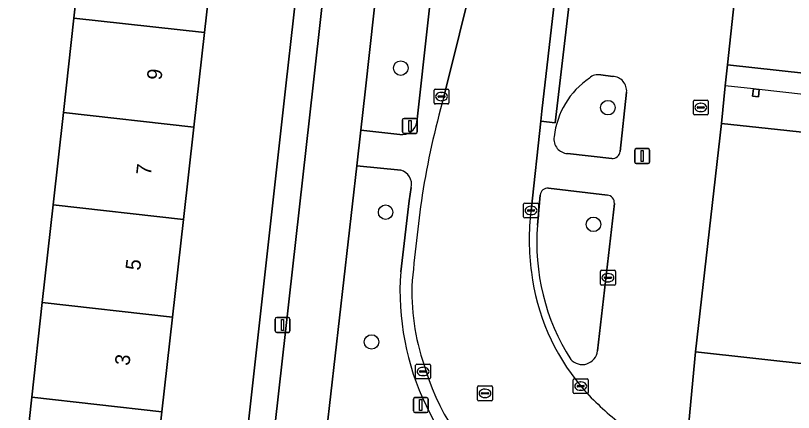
# Model space of a CAD drawing. Extents: x 162026 to 163502, y 387295 to 388169.
# Drawn here: x 162230.9 to 162283.3, y 387554 to 387580.7 of the extents above; entities that cross this region are included whole.
import ezdxf

# ---------------------------------------------------------------- set-up
doc = ezdxf.new("R2010")
doc.units = 0
for name, color, linetype in [('IMGEO_Berm_groen', 7, 'Continuous'), ('IMGEO_Boom', 7, 'Continuous'), ('IMGEO_Brandkraan', 7, 'Continuous'), ('IMGEO_Erf', 7, 'Continuous'), ('IMGEO_Fietspad_gesloten', 7, 'Continuous'), ('IMGEO_Groenvoorziening', 7, 'Continuous'), ('IMGEO_Kolk', 7, 'Continuous'), ('IMGEO_Lichtmast', 7, 'Continuous'), ('IMGEO_Pand', 7, 'Continuous'), ('IMGEO_Pand_nummerreeks', 7, 'Continuous'), ('IMGEO_Pand_overbouw', 7, 'Continuous'), ('IMGEO_Rijbaan_lokaal_gesloten', 7, 'Continuous'), ('IMGEO_Rijbaan_lokaal_open', 7, 'Continuous'), ('IMGEO_Rioolput', 7, 'Continuous'), ('IMGEO_Voetpad_gesloten', 7, 'Continuous'), ('IMGEO_Voetpad_open', 7, 'Continuous')]:
    doc.layers.add(name, color=color, linetype=linetype)

msp = doc.modelspace()

# ---------------------------------------------------------------- linework, layer by layer
at = {"layer": 'IMGEO_Berm_groen'}
for points in [[(162260.156, 387602.193), (162257.445, 387602.487), (162254.47, 387575.568), (162254.178, 387572.997), (162256.814, 387572.706)], [(162257.966, 387573.542), (162261.02, 387601.114)]]:
    msp.add_lwpolyline(points, dxfattribs=at)
msp.add_arc((162256.958, 387573.719), 1.023, 261.9126, 350.0237, dxfattribs=at)
at = {"layer": 'IMGEO_Boom'}
for centre in [(162256.873, 387577.172), (162270.837, 387574.509), (162255.854, 387567.469), (162269.863, 387566.651), (162254.903, 387558.729)]:
    msp.add_circle(centre, 0.489, dxfattribs=at)
at = {"layer": 'IMGEO_Brandkraan'}
for p, q in [((162276.595, 387574.097), (162276.595, 387574.949)), ((162276.67, 387575.023), (162277.522, 387575.023)), ((162277.083, 387574.803), (162277.108, 387574.803)), ((162277.596, 387574.949), (162277.596, 387574.097)), ((162276.854, 387574.517), (162276.854, 387574.529)), ((162277.292, 387574.48), (162276.894, 387574.48)), ((162276.897, 387574.566), (162277.295, 387574.566)), ((162277.106, 387574.243), (162277.081, 387574.243)), ((162277.338, 387574.529), (162277.338, 387574.517)), ((162277.522, 387574.023), (162276.67, 387574.023))]:
    msp.add_line(p, q, dxfattribs=at)
for points in [[(162276.595, 387574.097), (162276.595, 387574.949)], [(162276.67, 387575.023), (162277.522, 387575.023)], [(162277.596, 387574.949), (162277.596, 387574.097)], [(162277.522, 387574.023), (162276.67, 387574.023)]]:
    msp.add_lwpolyline(points, dxfattribs=at)
for centre, radius, start, end in [((162276.672, 387574.947), 0.0765, 91.552, 178.448), ((162276.672, 387574.947), 0.0765, 91.552, 178.448), ((162277.52, 387574.947), 0.0765, 1.552, 88.448), ((162277.52, 387574.947), 0.0765, 1.552, 88.448), ((162276.894, 387574.526), 0.0403, 85.8775, 175.7526), ((162276.891, 387574.516), 0.0366, 178.938, 274.7102), ((162277.295, 387574.523), 0.043, 264.8664, 352.4533), ((162277.299, 387574.528), 0.0386, 1.7309, 96.639), ((162276.672, 387574.099), 0.0765, 181.552, 268.448), ((162276.672, 387574.099), 0.0765, 181.552, 268.448), ((162277.52, 387574.099), 0.0765, 271.552, 358.448), ((162277.52, 387574.099), 0.0765, 271.552, 358.448)]:
    msp.add_arc(centre, radius, start, end, dxfattribs=at)
for centre, major_axis, ratio, start_param, end_param in [((162277.082, 387574.523), (-0.387, 0.002), 0.722429, 4.712389, 7.853982), ((162277.107, 387574.523), (-0.39, 0.002), 0.717154, 1.570796, 4.712389)]:
    msp.add_ellipse(centre, major_axis=major_axis, ratio=ratio, start_param=start_param, end_param=end_param, dxfattribs=at)
at = {"layer": 'IMGEO_Erf'}
for points in [[(162231.278, 387548.466), (162232.005, 387555.004), (162232.714, 387561.383), (162233.446, 387567.963), (162234.136, 387574.175), (162234.844, 387580.545), (162235.554, 387586.926), (162236.264, 387593.317), (162236.974, 387599.708), (162233.45, 387600.1), (162234.133, 387606.237), (162234.161, 387606.49), (162237.685, 387606.098), (162238.394, 387612.479), (162239.105, 387618.87), (162236.083, 387619.207), (162236.755, 387625.24), (162239.776, 387624.903), (162239.812, 387625.23), (162240.54, 387631.778), (162230.472, 387632.88)], [(162245.725, 387545.476), (162249.133, 387575.99), (162253.77, 387617.22), (162255.196, 387630.156), (162249.391, 387630.796), (162248.656, 387624.246), (162247.942, 387617.886), (162247.225, 387611.496), (162246.509, 387605.116), (162245.792, 387598.726), (162245.075, 387592.336), (162244.358, 387585.947), (162243.642, 387579.567), (162242.927, 387573.197), (162242.23, 387566.986), (162241.491, 387560.407), (162240.775, 387554.027), (162240.041, 387547.484)]]:
    msp.add_lwpolyline(points, dxfattribs=at)
at = {"layer": 'IMGEO_Fietspad_gesloten'}
msp.add_lwpolyline([(162249.002, 387527.305), (162250.593, 387541.437), (162251.213, 387546.944), (162251.283, 387547.562), (162253.903, 387570.582), (162254.178, 387572.997), (162254.47, 387575.568), (162257.445, 387602.487), (162257.74, 387604.874), (162260.472, 387629.489), (162260.746, 387631.878), (162262.605, 387648.82), (162263.515, 387657.112), (162260.081, 387657.552), (162255.563, 387617.085), (162250.964, 387576.026), (162247.716, 387547.043), (162245.412, 387526.736)], dxfattribs=at)
at = {"layer": 'IMGEO_Groenvoorziening'}
for points in [[(162271.159, 387576.617), (162270.351, 387576.709)], [(162271.664, 387571.56), (162272.097, 387575.545)], [(162268.107, 387571.421), (162271.091, 387571.092)], [(162256.879, 387570.293), (162253.903, 387570.582), (162251.283, 387547.562), (162254.148, 387547.245), (162255.721, 387547.048), (162268.163, 387545.52)], [(162256.87, 387563.453), (162257.433, 387568.234), (162257.579, 387569.13)], [(162270.803, 387568.62), (162266.833, 387569.082)], [(162266.268, 387568.621), (162266.088, 387566.604)], [(162270.145, 387558.124), (162271.27, 387568.06)]]:
    msp.add_lwpolyline(points, dxfattribs=at)
for centre, radius, start, end in [((162272.692, 387571.946), 5.511, 124.2618, 173.6784), ((162270.162, 387575.901), 0.83, 76.8476, 133.6881), ((162271.113, 387575.631), 0.988, 355.0317, 87.3402), ((162268.17, 387572.388), 0.97, 170.2251, 219.7285), ((162268.169, 387572.388), 0.969, 219.7795, 266.3545), ((162271.136, 387571.622), 0.532, 265.1894, 353.2913), ((162256.606, 387569.337), 0.995, 348.0097, 74.0771), ((162266.783, 387568.567), 0.518, 84.4254, 173.9986), ((162270.756, 387568.106), 0.516, 354.8288, 84.8226), ((162280.669, 387565.415), 14.63, 175.339, 212.4799), ((162274.616, 387562.147), 17.794, 175.7909, 235.5291), ((162269.108, 387558.255), 1.045, 221.7581, 352.7883)]:
    msp.add_arc(centre, radius, start, end, dxfattribs=at)
at = {"layer": 'IMGEO_Kolk'}
for p, q in [((162259.197, 387575.756), (162260.049, 387575.756)), ((162259.122, 387574.83), (162259.122, 387575.682)), ((162259.381, 387575.25), (162259.381, 387575.262)), ((162259.424, 387575.299), (162259.822, 387575.299)), ((162259.61, 387575.536), (162259.635, 387575.536)), ((162259.865, 387575.262), (162259.865, 387575.25)), ((162260.123, 387575.682), (162260.123, 387574.83)), ((162260.049, 387574.756), (162259.197, 387574.756)), ((162259.819, 387575.213), (162259.421, 387575.213)), ((162259.633, 387574.976), (162259.608, 387574.976)), ((162265.156, 387567.159), (162265.156, 387568.011)), ((162265.231, 387568.085), (162266.083, 387568.085)), ((162266.157, 387568.011), (162266.157, 387567.159)), ((162265.415, 387567.579), (162265.415, 387567.591)), ((162265.853, 387567.542), (162265.455, 387567.542)), ((162265.458, 387567.628), (162265.856, 387567.628)), ((162265.644, 387567.865), (162265.669, 387567.865)), ((162265.899, 387567.591), (162265.899, 387567.579)), ((162266.083, 387567.085), (162265.231, 387567.085)), ((162265.667, 387567.305), (162265.642, 387567.305)), ((162270.337, 387562.631), (162270.337, 387563.483)), ((162270.412, 387563.557), (162271.264, 387563.557)), ((162270.825, 387563.337), (162270.85, 387563.337)), ((162271.338, 387563.483), (162271.338, 387562.631)), ((162270.596, 387563.051), (162270.596, 387563.063)), ((162271.034, 387563.014), (162270.636, 387563.014)), ((162270.639, 387563.1), (162271.037, 387563.1)), ((162270.848, 387562.777), (162270.823, 387562.777)), ((162271.08, 387563.063), (162271.08, 387563.051)), ((162271.264, 387562.557), (162270.412, 387562.557)), ((162257.878, 387556.315), (162257.878, 387557.167)), ((162257.953, 387557.241), (162258.805, 387557.241)), ((162258.366, 387557.021), (162258.391, 387557.021)), ((162258.879, 387557.167), (162258.879, 387556.315)), ((162258.137, 387556.735), (162258.137, 387556.747)), ((162258.575, 387556.698), (162258.177, 387556.698)), ((162258.18, 387556.784), (162258.578, 387556.784)), ((162258.389, 387556.461), (162258.364, 387556.461)), ((162258.621, 387556.747), (162258.621, 387556.735)), ((162258.805, 387556.241), (162257.953, 387556.241)), ((162268.504, 387555.328), (162268.504, 387556.18)), ((162268.579, 387556.254), (162269.431, 387556.254)), ((162268.992, 387556.034), (162269.017, 387556.034)), ((162269.505, 387556.18), (162269.505, 387555.328)), ((162268.763, 387555.748), (162268.763, 387555.76)), ((162269.201, 387555.711), (162268.803, 387555.711)), ((162268.806, 387555.797), (162269.204, 387555.797)), ((162269.015, 387555.474), (162268.99, 387555.474)), ((162269.247, 387555.76), (162269.247, 387555.748)), ((162269.431, 387555.254), (162268.579, 387555.254))]:
    msp.add_line(p, q, dxfattribs=at)
for points in [[(162259.197, 387575.756), (162260.049, 387575.756)], [(162259.122, 387574.83), (162259.122, 387575.682)], [(162260.123, 387575.682), (162260.123, 387574.83)], [(162260.049, 387574.756), (162259.197, 387574.756)], [(162265.156, 387567.159), (162265.156, 387568.011)], [(162265.231, 387568.085), (162266.083, 387568.085)], [(162266.157, 387568.011), (162266.157, 387567.159)], [(162266.083, 387567.085), (162265.231, 387567.085)], [(162270.337, 387562.631), (162270.337, 387563.483)], [(162270.412, 387563.557), (162271.264, 387563.557)], [(162271.338, 387563.483), (162271.338, 387562.631)], [(162271.264, 387562.557), (162270.412, 387562.557)], [(162257.878, 387556.315), (162257.878, 387557.167)], [(162257.953, 387557.241), (162258.805, 387557.241)], [(162258.879, 387557.167), (162258.879, 387556.315)], [(162258.805, 387556.241), (162257.953, 387556.241)], [(162268.504, 387555.328), (162268.504, 387556.18)], [(162268.579, 387556.254), (162269.431, 387556.254)], [(162269.505, 387556.18), (162269.505, 387555.328)], [(162269.431, 387555.254), (162268.579, 387555.254)]]:
    msp.add_lwpolyline(points, dxfattribs=at)
for centre, radius, start, end in [((162259.199, 387575.68), 0.0765, 91.552, 178.448), ((162259.199, 387575.68), 0.0765, 91.552, 178.448), ((162260.047, 387575.68), 0.0765, 1.552, 88.448), ((162260.047, 387575.68), 0.0765, 1.552, 88.448), ((162259.421, 387575.259), 0.0403, 85.8775, 175.7526), ((162259.418, 387575.249), 0.0366, 178.938, 274.7102), ((162259.822, 387575.256), 0.043, 264.8664, 352.4533), ((162259.826, 387575.261), 0.0386, 1.7309, 96.639), ((162259.199, 387574.832), 0.0765, 181.552, 268.448), ((162259.199, 387574.832), 0.0765, 181.552, 268.448), ((162260.047, 387574.832), 0.0765, 271.552, 358.448), ((162260.047, 387574.832), 0.0765, 271.552, 358.448), ((162265.233, 387568.009), 0.0765, 91.552, 178.448), ((162265.233, 387568.009), 0.0765, 91.552, 178.448), ((162266.081, 387568.009), 0.0765, 1.552, 88.448), ((162266.081, 387568.009), 0.0765, 1.552, 88.448), ((162265.455, 387567.588), 0.0403, 85.8775, 175.7526), ((162265.452, 387567.578), 0.0366, 178.938, 274.7102), ((162265.856, 387567.585), 0.043, 264.8664, 352.4533), ((162265.86, 387567.59), 0.0386, 1.7309, 96.639), ((162265.233, 387567.161), 0.0765, 181.552, 268.448), ((162265.233, 387567.161), 0.0765, 181.552, 268.448), ((162266.081, 387567.161), 0.0765, 271.552, 358.448), ((162266.081, 387567.161), 0.0765, 271.552, 358.448), ((162270.414, 387563.481), 0.0765, 91.552, 178.448), ((162270.414, 387563.481), 0.0765, 91.552, 178.448), ((162271.262, 387563.481), 0.0765, 1.552, 88.448), ((162271.262, 387563.481), 0.0765, 1.552, 88.448), ((162270.636, 387563.06), 0.0403, 85.8775, 175.7526), ((162270.633, 387563.05), 0.0366, 178.938, 274.7102), ((162271.037, 387563.057), 0.043, 264.8664, 352.4533), ((162271.041, 387563.062), 0.0386, 1.7309, 96.639), ((162270.414, 387562.633), 0.0765, 181.552, 268.448), ((162270.414, 387562.633), 0.0765, 181.552, 268.448), ((162271.262, 387562.633), 0.0765, 271.552, 358.448), ((162271.262, 387562.633), 0.0765, 271.552, 358.448), ((162257.955, 387557.165), 0.0765, 91.552, 178.448), ((162257.955, 387557.165), 0.0765, 91.552, 178.448), ((162258.803, 387557.165), 0.0765, 1.552, 88.448), ((162258.803, 387557.165), 0.0765, 1.552, 88.448), ((162258.177, 387556.744), 0.0403, 85.8775, 175.7526), ((162258.174, 387556.734), 0.0366, 178.938, 274.7102), ((162258.578, 387556.741), 0.043, 264.8664, 352.4533), ((162258.582, 387556.746), 0.0386, 1.7309, 96.639), ((162257.955, 387556.317), 0.0765, 181.552, 268.448), ((162257.955, 387556.317), 0.0765, 181.552, 268.448), ((162258.803, 387556.317), 0.0765, 271.552, 358.448), ((162258.803, 387556.317), 0.0765, 271.552, 358.448), ((162268.581, 387556.178), 0.0765, 91.552, 178.448), ((162268.581, 387556.178), 0.0765, 91.552, 178.448), ((162269.429, 387556.178), 0.0765, 1.552, 88.448), ((162269.429, 387556.178), 0.0765, 1.552, 88.448), ((162268.581, 387555.33), 0.0765, 181.552, 268.448), ((162268.581, 387555.33), 0.0765, 181.552, 268.448), ((162268.803, 387555.757), 0.0403, 85.8775, 175.7526), ((162268.8, 387555.747), 0.0366, 178.938, 274.7102), ((162269.204, 387555.754), 0.043, 264.8664, 352.4533), ((162269.208, 387555.759), 0.0386, 1.7309, 96.639), ((162269.429, 387555.33), 0.0765, 271.552, 358.448), ((162269.429, 387555.33), 0.0765, 271.552, 358.448)]:
    msp.add_arc(centre, radius, start, end, dxfattribs=at)
for centre, major_axis, ratio, start_param, end_param in [((162259.609, 387575.256), (-0.387, 0.002), 0.722429, 4.712389, 7.853982), ((162259.634, 387575.256), (-0.39, 0.002), 0.717154, 1.570796, 4.712389), ((162265.643, 387567.585), (-0.387, 0.002), 0.722429, 4.712389, 7.853982), ((162265.668, 387567.585), (-0.39, 0.002), 0.717154, 1.570796, 4.712389), ((162270.824, 387563.057), (-0.387, 0.002), 0.722429, 4.712389, 7.853982), ((162270.849, 387563.057), (-0.39, 0.002), 0.717154, 1.570796, 4.712389), ((162258.365, 387556.741), (-0.387, 0.002), 0.722429, 4.712389, 7.853982), ((162258.39, 387556.741), (-0.39, 0.002), 0.717154, 1.570796, 4.712389), ((162268.991, 387555.754), (-0.387, 0.002), 0.722429, 4.712389, 7.853982), ((162269.016, 387555.754), (-0.39, 0.002), 0.717154, 1.570796, 4.712389)]:
    msp.add_ellipse(centre, major_axis=major_axis, ratio=ratio, start_param=start_param, end_param=end_param, dxfattribs=at)
at = {"layer": 'IMGEO_Lichtmast'}
for p, q in [((162256.994, 387572.88), (162256.994, 387573.68)), ((162256.994, 387573.68), (162256.994, 387572.88)), ((162257.094, 387573.78), (162257.884, 387573.78)), ((162257.884, 387573.78), (162257.094, 387573.78)), ((162257.984, 387573.68), (162257.984, 387572.88)), ((162257.984, 387572.88), (162257.984, 387573.68)), ((162257.884, 387572.78), (162257.094, 387572.78)), ((162257.094, 387572.78), (162257.884, 387572.78)), ((162272.652, 387570.849), (162272.652, 387571.649)), ((162272.652, 387571.649), (162272.652, 387570.849)), ((162272.752, 387571.749), (162273.542, 387571.749)), ((162273.542, 387571.749), (162272.752, 387571.749)), ((162273.642, 387571.649), (162273.642, 387570.849)), ((162273.642, 387570.849), (162273.642, 387571.649)), ((162273.542, 387570.749), (162272.752, 387570.749)), ((162272.752, 387570.749), (162273.542, 387570.749)), ((162248.41, 387559.475), (162248.41, 387560.275)), ((162248.41, 387560.275), (162248.41, 387559.475)), ((162248.51, 387560.375), (162249.3, 387560.375)), ((162249.3, 387560.375), (162248.51, 387560.375)), ((162249.4, 387560.275), (162249.4, 387559.475)), ((162249.4, 387559.475), (162249.4, 387560.275)), ((162249.3, 387559.375), (162248.51, 387559.375)), ((162248.51, 387559.375), (162249.3, 387559.375)), ((162257.728, 387554.083), (162257.728, 387554.883)), ((162257.728, 387554.883), (162257.728, 387554.083)), ((162257.828, 387554.983), (162258.618, 387554.983)), ((162258.618, 387554.983), (162257.828, 387554.983)), ((162258.718, 387554.883), (162258.718, 387554.083)), ((162258.718, 387554.083), (162258.718, 387554.883)), ((162258.618, 387553.983), (162257.828, 387553.983)), ((162257.828, 387553.983), (162258.618, 387553.983))]:
    msp.add_line(p, q, dxfattribs=at)
for points in [[(162257.414, 387573.655), (162257.564, 387573.655), (162257.564, 387572.905), (162257.414, 387572.905), (162257.414, 387573.655)], [(162273.072, 387571.624), (162273.222, 387571.624), (162273.222, 387570.874), (162273.072, 387570.874), (162273.072, 387571.624)], [(162248.83, 387560.25), (162248.98, 387560.25), (162248.98, 387559.5), (162248.83, 387559.5), (162248.83, 387560.25)], [(162258.148, 387554.858), (162258.298, 387554.858), (162258.298, 387554.108), (162258.148, 387554.108), (162258.148, 387554.858)]]:
    msp.add_lwpolyline(points, dxfattribs=at)
for centre, start, end in [((162257.094, 387573.68), 90, 180), ((162257.094, 387573.68), 90, 180), ((162257.884, 387573.68), 0, 90), ((162257.884, 387573.68), 360, 90), ((162257.094, 387572.88), 180, 270), ((162257.094, 387572.88), 180, 270), ((162257.884, 387572.88), 270, 0), ((162257.884, 387572.88), 270, 0), ((162272.752, 387571.649), 90, 180), ((162272.752, 387571.649), 90, 180), ((162273.542, 387571.649), 0, 90), ((162273.542, 387571.649), 360, 90), ((162272.752, 387570.849), 180, 270), ((162272.752, 387570.849), 180, 270), ((162273.542, 387570.849), 270, 0), ((162273.542, 387570.849), 270, 0), ((162248.51, 387560.275), 90, 180), ((162248.51, 387560.275), 90, 180), ((162249.3, 387560.275), 0, 90), ((162249.3, 387560.275), 360, 90), ((162248.51, 387559.475), 180, 270), ((162248.51, 387559.475), 180, 270), ((162249.3, 387559.475), 270, 0), ((162249.3, 387559.475), 270, 0), ((162257.828, 387554.883), 90, 180), ((162257.828, 387554.883), 90, 180), ((162258.618, 387554.883), 0, 90), ((162258.618, 387554.883), 360, 90), ((162257.828, 387554.083), 180, 270), ((162257.828, 387554.083), 180, 270), ((162258.618, 387554.083), 270, 0), ((162258.618, 387554.083), 270, 0)]:
    msp.add_arc(centre, 0.1, start, end, dxfattribs=at)
at = {"layer": 'IMGEO_Pand'}
for points in [[(162243.642, 387579.567), (162244.358, 387585.947), (162235.554, 387586.926), (162234.844, 387580.545)], [(162234.844, 387580.545), (162234.136, 387574.175), (162242.927, 387573.197), (162243.642, 387579.567)], [(162280.642, 387575.768), (162280.585, 387575.282), (162280.983, 387575.238), (162281.039, 387575.724)], [(162242.23, 387566.986), (162242.927, 387573.197), (162234.136, 387574.175), (162233.446, 387567.963)], [(162241.491, 387560.407), (162242.23, 387566.986), (162233.446, 387567.963), (162232.714, 387561.383)], [(162240.775, 387554.027), (162241.491, 387560.407), (162232.714, 387561.383), (162232.005, 387555.004)], [(162232.005, 387555.004), (162231.278, 387548.466), (162235.073, 387548.041), (162240.041, 387547.484), (162240.775, 387554.027)]]:
    msp.add_lwpolyline(points, close=True, dxfattribs=at)
msp.add_lwpolyline([(162287.507, 387572.471), (162278.491, 387573.437), (162276.745, 387558.061), (162370.078, 387547.752)], dxfattribs=at)
at = {"layer": 'IMGEO_Pand_overbouw'}
msp.add_lwpolyline([(162287.798, 387574.976), (162286.019, 387575.173), (162285.962, 387574.686), (162285.555, 387574.731), (162285.611, 387575.218), (162281.039, 387575.724), (162280.983, 387575.238), (162280.585, 387575.282), (162280.642, 387575.768), (162278.751, 387575.978), (162278.491, 387573.437), (162287.507, 387572.471)], close=True, dxfattribs=at)
at = {"layer": 'IMGEO_Rijbaan_lokaal_gesloten'}
for points in [[(162269.691, 387603.88), (162269.735, 387604.276), (162270.44, 387610.557), (162270.483, 387610.938), (162271.83, 387622.883), (162271.935, 387623.796), (162272.612, 387629.708), (162272.661, 387630.134), (162273.862, 387640.857), (162273.911, 387641.266), (162274.23, 387643.955), (162268.773, 387644.721), (162268.572, 387642.831), (162265.536, 387616.015), (162261.972, 387584.295), (162261.88, 387583.741), (162259.779, 387575.24)], [(162265.657, 387567.585), (162266.306, 387573.59), (162266.38, 387574.271), (162268.018, 387588.53), (162268.022, 387588.565), (162268.219, 387590.6), (162269.691, 387603.88)]]:
    msp.add_lwpolyline(points, dxfattribs=at)
for centre, radius, start, end in [((162315.734, 387559.408), 58.152, 164.20193, 170.8835), ((162381.224, 387551.423), 124.104, 172.03417, 174.88353), ((162281.058, 387565.591), 15.529, 172.6213, 188.0124), ((162280.361, 387565.232), 14.792, 187.0137, 219.8495), ((162273.357, 387562.202), 15.745, 178.9465, 200.001), ((162273.936, 387561.606), 16.104, 197.3042, 233.6718), ((162282.482, 387567.416), 17.822, 220.8686, 231.7265)]:
    msp.add_arc(centre, radius, start, end, dxfattribs=at)
at = {"layer": 'IMGEO_Rijbaan_lokaal_open'}
for points in [[(162279.501, 387583.06), (162278.897, 387577.398)], [(162278.897, 387577.398), (162328.456, 387571.969), (162328.303, 387570.491)]]:
    msp.add_lwpolyline(points, dxfattribs=at)
at = {"layer": 'IMGEO_Rioolput'}
for p, q in [((162262.052, 387554.843), (162262.052, 387555.695)), ((162262.127, 387555.769), (162262.979, 387555.769)), ((162262.354, 387555.312), (162262.752, 387555.312)), ((162262.54, 387555.549), (162262.565, 387555.549)), ((162263.053, 387555.695), (162263.053, 387554.843)), ((162262.311, 387555.263), (162262.311, 387555.275)), ((162262.749, 387555.226), (162262.351, 387555.226)), ((162262.563, 387554.989), (162262.538, 387554.989)), ((162262.795, 387555.275), (162262.795, 387555.263)), ((162262.979, 387554.769), (162262.127, 387554.769))]:
    msp.add_line(p, q, dxfattribs=at)
for points in [[(162262.052, 387554.843), (162262.052, 387555.695)], [(162262.127, 387555.769), (162262.979, 387555.769)], [(162263.053, 387555.695), (162263.053, 387554.843)], [(162262.979, 387554.769), (162262.127, 387554.769)]]:
    msp.add_lwpolyline(points, dxfattribs=at)
for centre, radius, start, end in [((162262.129, 387555.693), 0.0765, 91.552, 178.448), ((162262.129, 387555.693), 0.0765, 91.552, 178.448), ((162262.351, 387555.272), 0.0403, 85.8775, 175.7526), ((162262.756, 387555.274), 0.0386, 1.7309, 96.639), ((162262.977, 387555.693), 0.0765, 1.552, 88.448), ((162262.977, 387555.693), 0.0765, 1.552, 88.448), ((162262.129, 387554.845), 0.0765, 181.552, 268.448), ((162262.129, 387554.845), 0.0765, 181.552, 268.448), ((162262.348, 387555.262), 0.0366, 178.938, 274.7102), ((162262.752, 387555.269), 0.043, 264.8664, 352.4533), ((162262.977, 387554.845), 0.0765, 271.552, 358.448), ((162262.977, 387554.845), 0.0765, 271.552, 358.448)]:
    msp.add_arc(centre, radius, start, end, dxfattribs=at)
for centre, major_axis, ratio, start_param, end_param in [((162262.539, 387555.269), (-0.387, 0.002), 0.722429, 4.712389, 7.853982), ((162262.564, 387555.269), (-0.39, 0.002), 0.717154, 1.570796, 4.712389)]:
    msp.add_ellipse(centre, major_axis=major_axis, ratio=ratio, start_param=start_param, end_param=end_param, dxfattribs=at)
at = {"layer": 'IMGEO_Voetpad_gesloten'}
msp.add_lwpolyline([(162269.044, 387588.391), (162268.018, 387588.53), (162266.38, 387574.271), (162266.306, 387573.59), (162267.289, 387573.481)], close=True, dxfattribs=at)
at = {"layer": 'IMGEO_Voetpad_open'}
for points in [[(162257.61, 387652.066), (162255.366, 387631.702), (162255.196, 387630.156), (162253.77, 387617.22), (162249.133, 387575.99), (162245.725, 387545.476), (162245.563, 387544.042), (162242.363, 387515.983)], [(162276.084, 387551.129), (162276.745, 387558.061), (162278.491, 387573.437), (162278.751, 387575.978), (162278.897, 387577.398), (162279.501, 387583.06), (162279.706, 387584.469), (162284.468, 387626.843), (162285.173, 387631.635)], [(162245.412, 387526.736), (162247.716, 387547.043), (162250.964, 387576.026), (162255.563, 387617.085)], [(162261.02, 387601.114), (162257.966, 387573.542)], [(162268.219, 387590.6), (162268.022, 387588.565), (162268.018, 387588.53), (162269.044, 387588.391), (162267.289, 387573.481), (162266.306, 387573.59), (162265.657, 387567.585)], [(162259.779, 387575.24), (162261.88, 387583.741), (162261.972, 387584.295)], [(162270.351, 387576.709), (162271.159, 387576.617)], [(162272.097, 387575.545), (162271.664, 387571.56)], [(162256.814, 387572.706), (162254.178, 387572.997), (162253.903, 387570.582), (162256.879, 387570.293)], [(162271.091, 387571.092), (162268.107, 387571.421)], [(162257.579, 387569.13), (162257.433, 387568.234), (162256.87, 387563.453)], [(162266.833, 387569.082), (162270.803, 387568.62)], [(162266.088, 387566.604), (162266.268, 387568.621)], [(162271.27, 387568.06), (162270.145, 387558.124)], [(162370.078, 387547.752), (162276.745, 387558.061), (162276.084, 387551.129)]]:
    msp.add_lwpolyline(points, dxfattribs=at)
for points in [[(162278.897, 387577.398), (162278.751, 387575.978), (162278.491, 387573.437), (162287.507, 387572.471), (162287.798, 387574.976), (162328.303, 387570.491), (162328.456, 387571.969)], [(162280.642, 387575.768), (162281.039, 387575.724), (162280.983, 387575.238), (162280.585, 387575.282)]]:
    msp.add_lwpolyline(points, close=True, dxfattribs=at)
for centre, radius, start, end in [((162272.692, 387571.946), 5.511, 124.2618, 173.6784), ((162270.162, 387575.901), 0.83, 76.8476, 133.6881), ((162271.113, 387575.631), 0.988, 355.0317, 87.3402), ((162315.734, 387559.408), 58.152, 164.20193, 170.8835), ((162256.958, 387573.719), 1.023, 261.9126, 350.0237), ((162268.17, 387572.388), 0.97, 170.2251, 219.7285), ((162268.169, 387572.388), 0.969, 219.7795, 266.3545), ((162271.136, 387571.622), 0.532, 265.1894, 353.2913), ((162256.606, 387569.337), 0.995, 348.0097, 74.0771), ((162266.783, 387568.567), 0.518, 84.4254, 173.9986), ((162381.224, 387551.423), 124.104, 172.03417, 174.88353), ((162270.756, 387568.106), 0.516, 354.8288, 84.8226), ((162281.058, 387565.591), 15.529, 172.6213, 188.0124), ((162280.669, 387565.415), 14.63, 175.339, 212.4799), ((162274.616, 387562.147), 17.794, 175.7909, 235.5291), ((162280.361, 387565.232), 14.792, 187.0137, 219.8495), ((162273.357, 387562.202), 15.745, 178.9465, 200.001), ((162269.108, 387558.255), 1.045, 221.7581, 352.7883), ((162273.936, 387561.606), 16.104, 197.3042, 233.6718), ((162282.482, 387567.416), 17.822, 220.8686, 231.7265)]:
    msp.add_arc(centre, radius, start, end, dxfattribs=at)

# ---------------------------------------------------------------- texts
at = {"layer": 'IMGEO_Pand_nummerreeks'}
for s, p in [('9', (162240.743, 387576.33)), ('7', (162240.023, 387569.922)), ('5', (162239.304, 387563.513)), ('3', (162238.585, 387557.104))]:
    msp.add_text(s, height=1, rotation=83.5966, dxfattribs=at).set_placement(p)

doc.saveas('drawing.dxf')
